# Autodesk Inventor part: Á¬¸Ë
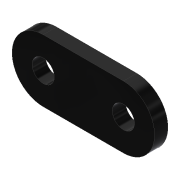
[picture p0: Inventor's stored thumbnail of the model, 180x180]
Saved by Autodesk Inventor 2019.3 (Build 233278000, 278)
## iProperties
Created: 2017-10
Part Number: Á¬¸Ë
Material: Ogólny
Document SubType Name: Modeling
Designer: CADENGINEERING4
Density: 1 g/cm^3
Appearance: Gładki — czarny
Author: CADENGINEERING4
Revision Number: ÈÎºÎ
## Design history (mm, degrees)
feature "Í¹Ì¨-À­Éì1"
node "Bryła1"
